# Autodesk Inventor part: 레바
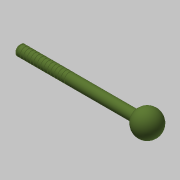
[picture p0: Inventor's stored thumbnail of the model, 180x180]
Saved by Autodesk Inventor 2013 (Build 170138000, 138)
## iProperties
Created: 2015-12
Part Number: 레바
Material: 스테인리스강
Document SubType Name: Modeling
Designer: mduedu
Density: 8.08 g/cm^3
Mass: 29.6046 g
Surface Area: 20.4663 cm^2
Volume: 3.66393 cm^3
Author: mduedu
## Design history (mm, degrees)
sketch "스케치1"
  geometry: C1 r 3 at (0, 0); 1 further point
  constraints: 1 centre point, 1 coincident
  dimensions: "d0" = 6 diameter of C1
extrude "돌출1" new body sketch "스케치1" distance "d1" = 75; taper "d2" = 0 deg
sketch "스케치2"
  geometry: L1 (7.5, 0)-(-6, 0); L2 (-6, 4.5)-(-6, 0); A1 r 7.5 centre (0, 0) between (7.5, 0) and (-6, 4.5); 2 further points
  constraints: 4 end point, 2 coincident, 2 point on circle, 1 centre point, 1 horizontal, 1 perpendicular, 1 point on line
  dimensions: "d3" = 15 diameter of A1; "d10" = 6 distance from line of L2 point (0, 0)
revolve "회전1" sketch "스케치2" stored, may be unused: angle "d4" = 90 deg
chamfer "모따기1" distance "d7" = 0.5; stored, may be unused: second distance "d8" = 2, angle "d9" = 45 deg
fillet "모깎기2" dims "d11" = 0.3
sketch "스케치4"
  geometry: L1 (-75, -2.5)-(-75, 2.5) reference; L2 (-75, 0)-(0, 0); L3 (-6.3, 3)-(-74.5, 3) reference; L4 (-74, 3)-(-73.9, 3); L5 (-73.9, 3)-(-73.9, 2.9); L6 (-73.9, 2.9)-(-74, 2.9); L7 (-74, 2.9)-(-74, 3)
  constraints: 10 end point, 2 parallel, 2 perpendicular, 1 horizontal, 1 midpoint, 1 point on line
  dimensions: "d17" = 1 distance between parallel lines of L7 L1; "d18" = 0.1 distance of L5.end L6.end; "d19" = 0.1 distance of L4.end L5.end
revolve "회전3" sketch "스케치4" stored, may be unused: angle "d20" = 90 deg
node "솔리드1"
pattern_linear "직사각형 패턴1" dims "d23" = 2
